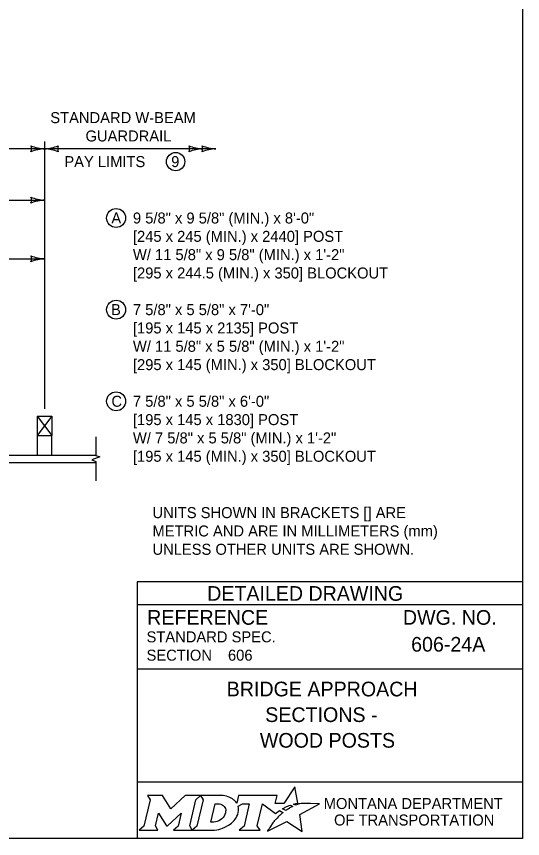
# Model space of a CAD drawing. Extents: x 49991.4 to 50021, y 49987.6 to 50011.4.
# Drawn here: x 50013.991 to 50016.75, y 49987.799 to 49992.285 of the extents above; entities that cross this region are included whole.
import ezdxf

# ---------------------------------------------------------------- set-up
doc = ezdxf.new("R2010")
doc.units = 0
for name, color, linetype in [('Default', 7, 'Continuous'), ('Level 1', 7, 'Continuous'), ('Level 2', 7, 'Continuous'), ('Level 3', 7, 'Continuous'), ('Level 5', 7, 'Continuous'), ('Level 6', 7, 'Continuous')]:
    doc.layers.add(name, color=color, linetype=linetype)

msp = doc.modelspace()

# ---------------------------------------------------------------- linework, layer by layer
at = {"layer": 'Default'}
for points in [[(50015.5126, 49987.9811), (50015.5023, 49987.9867), (50015.5139, 49987.9895), (50015.5255, 49987.9915), (50015.5081, 49988.0816), (50015.4486, 49987.9903), (50015.4013, 49987.9896), (50015.4116, 49988.0337), (50015.2024, 49988.0338), (50015.1923, 49987.9913), (50015.1865, 49987.9996)], [(50014.7056, 49988.0338), (50014.7197, 49988.0104), (50014.6862, 49987.8671), (50014.6605, 49987.8446), (50014.7621, 49987.8446), (50014.7486, 49987.8674), (50014.7648, 49987.9375), (50014.8085, 49987.8685), (50014.8138, 49987.8685), (50014.8889, 49987.938), (50014.8725, 49987.8669), (50014.8478, 49987.8449), (50014.9494, 49987.8449), (50014.9356, 49987.8682), (50014.9688, 49988.0106)], [(50014.9688, 49988.0106), (50014.9941, 49988.0338), (50014.9117, 49988.0338), (50014.8321, 49987.9608), (50014.7876, 49988.0335), (50014.7056, 49988.0338)], [(50015.1077, 49988.0338), (50014.9941, 49988.0338), (50015.0088, 49988.0109), (50014.9749, 49987.8671), (50014.9494, 49987.8449), (50015.06, 49987.8449)], [(50015.1317, 49987.9471), (50015.1305, 49987.939), (50015.1273, 49987.9297), (50015.1231, 49987.9215), (50015.1175, 49987.914), (50015.111, 49987.9071), (50015.1031, 49987.9008), (50015.0948, 49987.8961), (50015.0857, 49987.8922), (50015.0766, 49987.8899), (50015.0674, 49987.889), (50015.0515, 49987.889), (50015.0751, 49987.989), (50015.0911, 49987.989), (50015.0987, 49987.9884), (50015.1063, 49987.9865), (50015.1129, 49987.9835), (50015.119, 49987.9793), (50015.1238, 49987.9743), (50015.1275, 49987.9683), (50015.1302, 49987.9621), (50015.1318, 49987.9547), (50015.1318, 49987.9517), (50015.1317, 49987.9471)], [(50015.1991, 49987.9747), (50015.2237, 49987.9878), (50015.2606, 49987.9878), (50015.232, 49987.8673), (50015.2045, 49987.8446), (50015.3207, 49987.8446), (50015.3037, 49987.8675), (50015.3319, 49987.9877), (50015.4032, 49987.936), (50015.4243, 49987.9511), (50015.444, 49987.9402)], [(50015.3882, 49987.8843), (50015.3729, 49987.8599), (50015.3682, 49987.8524), (50015.3624, 49987.8438), (50015.3601, 49987.8395), (50015.4654, 49987.8926), (50015.5493, 49987.8375), (50015.5362, 49987.9302), (50015.6431, 49987.9886), (50015.5938, 49987.9894), (50015.5637, 49987.9898), (50015.5429, 49987.9901), (50015.5361, 49987.9886), (50015.5312, 49987.9874), (50015.5228, 49987.9851), (50015.5126, 49987.9811)], [(50015.4622, 49987.9535), (50015.4598, 49987.9518), (50015.4415, 49987.9614), (50015.4518, 49987.9671), (50015.4559, 49987.9693), (50015.4645, 49987.9733), (50015.4702, 49987.9759), (50015.4781, 49987.9789), (50015.4854, 49987.9816), (50015.4972, 49987.9742), (50015.4932, 49987.9721), (50015.4886, 49987.9696), (50015.4844, 49987.9674), (50015.4794, 49987.9645), (50015.4775, 49987.9634), (50015.4748, 49987.9618), (50015.4723, 49987.9604), (50015.47, 49987.9588), (50015.4674, 49987.957), (50015.4647, 49987.9552), (50015.4622, 49987.9535)], [(50015.4021, 49987.9004), (50015.4021, 49987.9004)], [(50015.1057, 49987.8522), (50015.1141, 49987.8548), (50015.1271, 49987.8602), (50015.1475, 49987.8712)]]:
    msp.add_lwpolyline(points, dxfattribs=at)
for centre, radius, start, end in [((50015.1308, 49987.9554), 0.0709, 339.5329, 15.8582), ((50015.0868, 49987.9727), 0.1183, 300.9103, 339.1383)]:
    msp.add_arc(centre, radius, start, end, dxfattribs=at)
for centre, major_axis, ratio, start_param, end_param in [((50015.1056, 49987.9864), (0.0834, -0.0037), 0.568097, 0.61298, 1.570796), ((50015.1612, 49987.9937), (0.0361, -0.0295), 0.469099, 1.225588, 1.570796), ((50015.4329, 49987.9305), (-0.0112, -0.0097), 0.021651, 3.157348, 6.283185), ((50015.3952, 49987.8923), (-0.00694, -0.00806), 0.008222, 0, 3.137361), ((50015.4119, 49987.9106), (-0.0098, -0.0102), 0.016458, 3.141593, 6.279097), ((50015.0603, 49987.9932), (0, 0.1484), 0.987302, 3.139398, 3.456847)]:
    msp.add_ellipse(centre, major_axis=major_axis, ratio=ratio, start_param=start_param, end_param=end_param, dxfattribs=at)
at = {"layer": 'Level 1'}
for p, q in [((50014.1049, 49990.1043), (50014.1049, 49989.9976)), ((50014.1049, 49990.1043), (50014.185, 49990.1043)), ((50014.185, 49990.1043), (50014.1049, 49989.9976)), ((50014.1049, 49990.1043), (50014.185, 49989.9976)), ((50014.185, 49990.1043), (50014.185, 49989.9976)), ((50014.1049, 49989.9979), (50014.1049, 49989.8909)), ((50014.1049, 49989.9976), (50014.185, 49989.9976)), ((50014.185, 49989.8909), (50014.185, 49989.9976)), ((50009.2441, 49989.8909), (50014.424, 49989.8909)), ((50009.2441, 49989.8508), (50014.424, 49989.8508))]:
    msp.add_line(p, q, dxfattribs=at)
msp.add_lwpolyline([(49999.3835, 49998.9992), (50016.7501, 49998.9992), (50016.7501, 49987.7988), (49999.3835, 49987.7988)], close=True, dxfattribs=at)
at = {"layer": 'Level 2'}
for centre, radius in [((50014.859, 49991.4924), 0.05), ((50014.5344, 49991.1847), 0.0517), ((50014.5344, 49990.6847), 0.0517), ((50014.5344, 49990.1847), 0.0517)]:
    msp.add_circle(centre, radius, dxfattribs=at)
at = {"layer": 'Level 3'}
for p, q in [((50014.1447, 49991.6024), (50014.1447, 49990.1444)), ((50014.1448, 49991.5624), (50010.1426, 49991.5624)), ((50015.0778, 49991.5624), (50014.1447, 49991.5624)), ((50011.6435, 49991.2823), (50014.1447, 49991.2823)), ((50013.6444, 49990.9623), (50014.1447, 49990.9623))]:
    msp.add_line(p, q, dxfattribs=at)
for centre, radius, start, end in [((50014.1536, 49991.7789), 0.2167, 247.456, 267.6395), ((50014.0197, 49991.5624), 0.0534, 342.1388, 17.8612), ((50014.1559, 49991.3355), 0.2271, 92.8273, 112.0772), ((50014.1335, 49991.7892), 0.2271, 272.8273, 292.0772), ((50014.1358, 49991.3458), 0.2167, 67.456, 87.6395), ((50014.2697, 49991.5624), 0.0534, 162.1388, 197.8612), ((50015.0151, 49991.7789), 0.2167, 247.456, 267.6395), ((50014.8812, 49991.5624), 0.0534, 342.1388, 17.8612), ((50015.0174, 49991.3355), 0.2271, 92.8273, 112.0772), ((50015.0867, 49991.7789), 0.2167, 247.456, 267.6395), ((50014.9528, 49991.5624), 0.0534, 342.1388, 17.8612), ((50015.089, 49991.3355), 0.2271, 92.8273, 112.0772), ((50014.1536, 49991.4988), 0.2167, 247.456, 267.6395), ((50014.0197, 49991.2823), 0.0534, 342.1388, 17.8612), ((50014.1559, 49991.0555), 0.2271, 92.8273, 112.0772), ((50014.1536, 49991.1788), 0.2167, 247.456, 267.6395), ((50014.0197, 49990.9623), 0.0534, 342.1388, 17.8612), ((50014.1559, 49990.7355), 0.2271, 92.8273, 112.0772)]:
    msp.add_arc(centre, radius, start, end, dxfattribs=at)
at = {"layer": 'Level 5'}
for p, q in [((50016.7501, 49989.1988), (50014.6501, 49989.1988)), ((50014.6501, 49989.1988), (50014.6501, 49987.7988)), ((50016.7501, 49989.0738), (50014.6501, 49989.0738)), ((50016.3862, 49988.8587), (50016.3862, 49988.8587)), ((50015.1444, 49988.7993), (50015.1444, 49988.7993)), ((50016.7501, 49988.7238), (50014.6501, 49988.7238)), ((50015.7001, 49988.4747), (50015.7001, 49988.4747)), ((50016.7501, 49988.1057), (50014.6501, 49988.1057))]:
    msp.add_line(p, q, dxfattribs=at)
at = {"layer": 'Level 6'}
for p, q in [((50014.424, 49989.9909), (50014.424, 49989.8886)), ((50014.4462, 49989.8807), (50014.4018, 49989.8649)), ((50014.4018, 49989.8649), (50014.424, 49989.857)), ((50014.424, 49989.8886), (50014.4462, 49989.8807)), ((50014.424, 49989.857), (50014.424, 49989.7508))]:
    msp.add_line(p, q, dxfattribs=at)

# ---------------------------------------------------------------- texts
at = {"layer": 'Default'}
for s, p in [('MONTANA DEPARTMENT', (50015.6663, 49987.96)), ('OF TRANSPORTATION', (50015.7225, 49987.87))]:
    msp.add_text(s, height=0.06, dxfattribs=at).set_placement(p)
at = {"layer": 'Level 2'}
for s, height, p in [('STANDARD W-BEAM', 0.06, (50014.1758, 49991.7024)), ('GUARDRAIL', 0.06, (50014.3678, 49991.6024)), ('PAY LIMITS', 0.06, (50014.2522, 49991.4624)), ('9', 0.06, (50014.8346, 49991.4624)), ('A', 0.06, (50014.5087, 49991.1548)), ('9 5/8" x 9 5/8" (MIN.) x 8\'-0" ', 0.06, (50014.6262, 49991.1547)), ('[245 x 245 (MIN.) x 2440] POST', 0.06, (50014.6262, 49991.0547)), ('W/ 11 5/8" x 9 5/8" (MIN.) x 1\'-2" ', 0.06, (50014.6262, 49990.9547)), ('[295 x 244.5 (MIN.) x 350] BLOCKOUT', 0.06, (50014.6262, 49990.8547)), ('B', 0.06, (50014.5068, 49990.6548)), ('7 5/8" x 5 5/8" x 7\'-0" ', 0.06, (50014.6262, 49990.6547)), ('[195 x 145 x 2135] POST ', 0.06, (50014.6262, 49990.5547)), ('W/ 11 5/8" x 5 5/8" (MIN.) x 1\'-2" ', 0.06, (50014.6262, 49990.4547)), ('[295 x 145 (MIN.) x 350] BLOCKOUT ', 0.06, (50014.6262, 49990.3547)), ('C', 0.06, (50014.509, 49990.1548)), ('7 5/8" x 5 5/8" x 6\'-0" ', 0.06, (50014.6262, 49990.1547)), ('[195 x 145 x 1830] POST ', 0.06, (50014.6262, 49990.0547)), ('W/ 7 5/8" x 5 5/8" (MIN.) x 1\'-2" ', 0.06, (50014.6262, 49989.9547)), ('[195 x 145 (MIN.) x 350] BLOCKOUT', 0.06, (50014.6262, 49989.8547)), ('UNITS SHOWN IN BRACKETS [] ARE ', 0.06, (50014.7326, 49989.5471)), ('METRIC AND ARE IN MILLIMETERS (mm) ', 0.06, (50014.7326, 49989.4471)), ('UNLESS OTHER UNITS ARE SHOWN.', 0.06, (50014.7326, 49989.3471)), ('606-24A', 0.08, (50016.1428, 49988.8187)), ('606', 0.06, (50015.1444, 49988.7693)), ('BRIDGE APPROACH', 0.08, (50015.1375, 49988.5747)), ('SECTIONS -', 0.08, (50015.3474, 49988.4347)), ('WOOD POSTS', 0.08, (50015.3181, 49988.2947))]:
    msp.add_text(s, height=height, dxfattribs=at).set_placement(p)
at = {"layer": 'Level 5'}
for s, height, p in [('DETAILED DRAWING', 0.0799, (50015.0311, 49989.0963)), ('REFERENCE', 0.08, (50014.7037, 49988.9654)), ('DWG. NO.', 0.08, (50016.0979, 49988.9654)), ('STANDARD SPEC.', 0.06, (50014.7004, 49988.8694)), ('SECTION', 0.06, (50014.7004, 49988.7694))]:
    msp.add_text(s, height=height, dxfattribs=at).set_placement(p)

doc.saveas('drawing.dxf')
